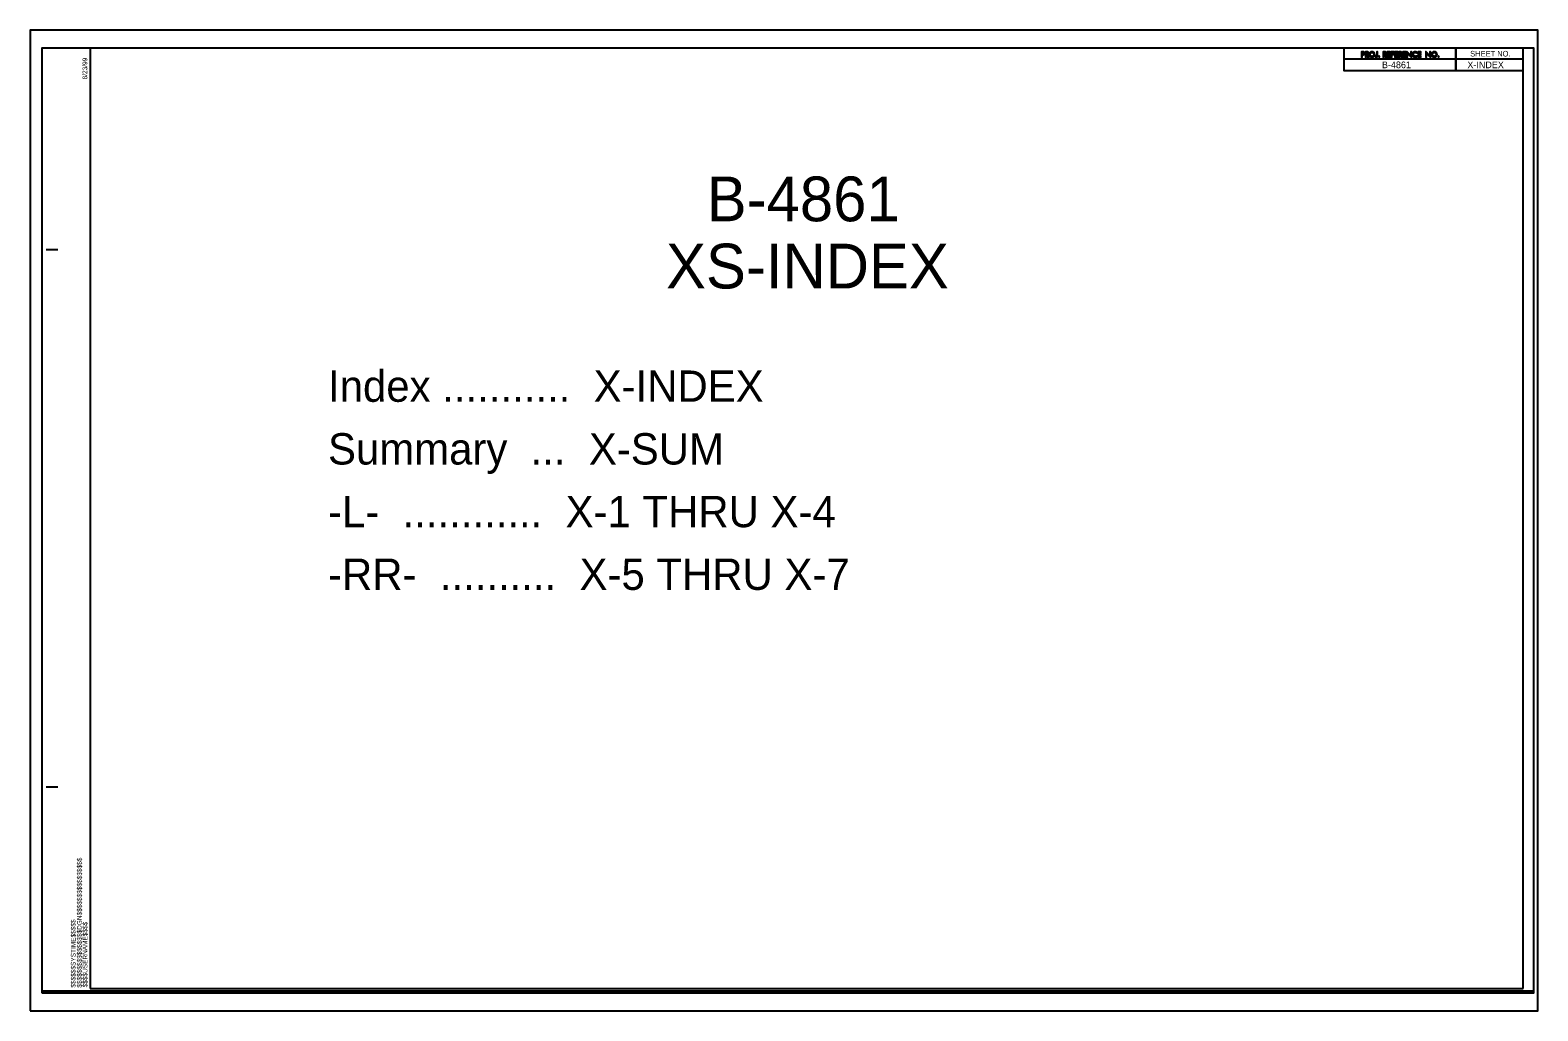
# Model space of a CAD drawing. Extents: x -13 to 323, y -5 to 214.
import ezdxf

# ---------------------------------------------------------------- set-up
doc = ezdxf.new("R2010")
doc.units = 0
for name, color, linetype in [('Old_Level_18', 7, 'Continuous'), ('Old_Level_2', 7, 'Continuous'), ('Old_Level_40', 7, 'Continuous'), ('Old_Level_41', 7, 'Continuous'), ('Old_Level_50', 7, 'Continuous'), ('Old_Level_51', 7, 'Continuous'), ('Old_Level_52', 7, 'Continuous'), ('Sheet Plot Border Inside CELL', 7, 'Continuous')]:
    doc.layers.add(name, color=color, linetype=linetype)

msp = doc.modelspace()

# ---------------------------------------------------------------- linework, layer by layer
at = {"layer": 'Old_Level_18'}
for p, q in [((320, 210), (0, 210)), ((0, 210), (0, 0)), ((320, 0), (320, 210)), ((0, 0), (0, 0)), ((0, 0), (320, 0))]:
    msp.add_line(p, q, dxfattribs=at)
at = {"layer": 'Old_Level_40'}
for p, q in [((305, 210), (305, 205)), ((305, 205), (305, 210)), ((280, 207.5), (280, 205)), ((320, 207.49), (280, 207.49)), ((280, 205), (320, 205)), ((0, 0), (0, 0)), ((0, 0), (0, 0)), ((0, 0), (0, 0)), ((0, 0), (0, 0)), ((0, 0), (0, 0))]:
    msp.add_line(p, q, dxfattribs=at)
for points in [[(320, 210), (280, 210), (280, 205), (320, 205)], [(283.9045, 208.5146), (283.9045, 207.99), (284.0817, 207.99), (284.0817, 208.5146), (284.1548, 208.5146), (284.3139, 208.5176), (284.4325, 208.5449), (284.5272, 208.6135), (284.5579, 208.6703), (284.0939, 208.6703), (284.0939, 208.6707), (284.0939, 208.676), (284.0939, 208.7017), (284.0939, 208.7165), (284.0939, 208.7604), (284.0939, 208.8377), (284.0939, 208.8438), (284.0939, 208.9199), (284.0939, 208.9589), (284.0939, 208.9733), (284.0939, 208.993), (284.0939, 208.996), (284.5628, 208.996), (284.5272, 209.062), (284.4325, 209.1301), (284.3139, 209.1574), (284.1548, 209.1604), (283.9045, 209.1604), (283.9045, 209.1574), (283.9045, 209.1301), (283.9045, 209.062), (283.9045, 208.996), (283.9045, 208.993), (283.9045, 208.9733), (283.9045, 208.9589), (283.9045, 208.9199), (283.9045, 208.8438), (283.9045, 208.8377), (283.9045, 208.7604), (283.9045, 208.7165), (283.9045, 208.7017), (283.9045, 208.676), (283.9045, 208.6707), (283.9045, 208.6703), (283.9045, 208.6135), (283.9045, 208.5449), (283.9045, 208.5176)], [(284.3605, 208.7165), (284.3492, 208.7017), (284.5747, 208.7017), (284.5829, 208.7165), (284.5899, 208.7604), (284.6026, 208.8377), (284.6014, 208.8438), (284.5891, 208.9199), (284.5829, 208.9589), (284.5751, 208.9733), (284.5749, 208.9733), (284.5643, 208.993), (284.5628, 208.996), (284.1435, 208.996), (284.2457, 208.993), (284.3283, 208.9733), (284.3431, 208.9589), (284.3836, 208.9199), (284.406, 208.8438), (284.405, 208.8377), (284.3946, 208.7604)], [(284.7757, 208.5142), (284.7757, 207.99), (284.9529, 207.99), (284.9529, 208.5142), (285.1825, 208.5142), (285.1768, 208.5218), (285.2188, 208.5294), (285.301, 208.5578), (285.3791, 208.6192), (285.3993, 208.6608), (284.9647, 208.6608), (284.9647, 208.6612), (284.9647, 208.6665), (284.9647, 208.693), (284.9647, 208.7165), (284.9647, 208.7544), (284.9647, 208.8377), (284.9647, 208.8381), (284.9647, 208.9173), (284.9647, 208.9585), (284.9647, 208.9729), (284.9647, 208.993), (284.9647, 208.9964), (285.4035, 208.9964), (285.3711, 209.0555), (285.2832, 209.1237), (285.1802, 209.1532), (285.0408, 209.1604), (284.7757, 209.1604), (284.7757, 209.1532), (284.7757, 209.1237), (284.7757, 209.0555), (284.7757, 208.9964), (284.7757, 208.993), (284.7757, 208.9729), (284.7757, 208.9585), (284.7757, 208.9173), (284.7757, 208.8381), (284.7757, 208.8377), (284.7757, 208.7544), (284.7757, 208.7165), (284.7757, 208.693), (284.7757, 208.6665), (284.7757, 208.6612), (284.7757, 208.6608), (284.7757, 208.6192), (284.7757, 208.5578), (284.7757, 208.5294), (284.7757, 208.5218)], [(284.9995, 208.9964), (285.0965, 208.993), (285.4054, 208.993), (285.4035, 208.9964)], [(285.2115, 208.7165), (285.195, 208.693), (285.4152, 208.693), (285.4268, 208.7165), (285.4321, 208.7544), (285.4438, 208.8377), (285.4436, 208.8381), (285.431, 208.9173), (285.4245, 208.9585), (285.4166, 208.9729), (285.4054, 208.993), (285.0963, 208.993), (285.1749, 208.9729), (285.1883, 208.9585), (285.2276, 208.9173), (285.2488, 208.8381), (285.2486, 208.8377), (285.2382, 208.7544)], [(286.026, 208.007), (286.2662, 207.9597), (286.5063, 208.007), (286.7016, 208.1351), (286.2658, 208.1351), (286.2436, 208.1396), (286.1018, 208.1688), (285.9639, 208.2635), (285.9147, 208.3389), (285.9145, 208.3389), (285.8703, 208.4067), (285.8385, 208.5726), (285.8385, 208.5733), (285.8703, 208.7392), (285.915, 208.8078), (285.9149, 208.8078), (285.9639, 208.8828), (286.1018, 208.9775), (286.2438, 209.007), (286.2658, 209.0116), (286.7016, 209.0116), (286.5063, 209.14), (286.0258, 209.14), (285.8306, 209.0116), (285.8238, 209.007), (285.8035, 208.9775), (285.7389, 208.8828), (285.6878, 208.8078), (285.6741, 208.7392), (285.6412, 208.5733), (285.6412, 208.5726), (285.6741, 208.4067), (285.6878, 208.3389), (285.7391, 208.2635), (285.8037, 208.1688), (285.8238, 208.1396), (285.8306, 208.1351)], [(286.266, 209.187), (286.026, 209.14), (286.5063, 209.14), (286.2662, 209.187)], [(286.2876, 209.007), (286.4298, 208.9775), (286.7287, 208.9775), (286.7086, 209.007), (286.7016, 209.0116), (286.2656, 209.0116)], [(286.2878, 208.1396), (286.2658, 208.1351), (286.7016, 208.1351), (286.7086, 208.1396), (286.7285, 208.1688), (286.7931, 208.2635), (286.8446, 208.3389), (286.858, 208.4067), (286.891, 208.5726), (286.8912, 208.5733), (286.8582, 208.7392), (286.858, 208.7392), (286.8446, 208.8078), (286.7932, 208.8828), (286.7287, 208.9775), (286.4296, 208.9775), (286.5681, 208.8828), (286.6169, 208.8078), (286.6616, 208.7392), (286.6932, 208.5733), (286.6934, 208.5726), (286.6616, 208.4067), (286.6173, 208.3389), (286.5681, 208.2635), (286.4298, 208.1688)], [(287.2506, 208.1461), (287.2173, 208.1366), (287.4927, 208.1366), (287.4965, 208.1461), (287.4983, 208.151), (287.4991, 208.1525), (287.5001, 208.1741), (287.4999, 208.1741), (287.5006, 208.1873), (287.5031, 208.2461), (287.5033, 208.2476), (287.5033, 208.3086), (287.5033, 209.1604), (287.3143, 209.1604), (287.3143, 208.3086), (287.3131, 208.2476), (287.3131, 208.2461), (287.3006, 208.1873), (287.2887, 208.1741), (287.2694, 208.1525), (287.2681, 208.151)], [(288.7417, 208.5142), (288.7417, 207.99), (288.919, 207.99), (288.919, 208.5142), (289.1485, 208.5142), (289.1428, 208.5218), (289.1849, 208.5294), (289.2671, 208.5578), (289.3451, 208.6192), (289.3654, 208.6608), (288.9307, 208.6608), (288.9307, 208.6612), (288.9307, 208.6665), (288.9307, 208.693), (288.9307, 208.7165), (288.9307, 208.7544), (288.9307, 208.8377), (288.9307, 208.8381), (288.9307, 208.9173), (288.9307, 208.9585), (288.9307, 208.9729), (288.9307, 208.993), (288.9307, 208.9964), (289.3695, 208.9964), (289.3371, 209.0555), (289.2493, 209.1237), (289.1462, 209.1532), (289.0068, 209.1604), (288.7417, 209.1604), (288.7417, 209.1532), (288.7417, 209.1237), (288.7417, 209.0555), (288.7417, 208.9964), (288.7417, 208.993), (288.7417, 208.9729), (288.7417, 208.9585), (288.7417, 208.9173), (288.7417, 208.8381), (288.7417, 208.8377), (288.7417, 208.7544), (288.7417, 208.7165), (288.7417, 208.693), (288.7417, 208.6665), (288.7417, 208.6612), (288.7417, 208.6608), (288.7417, 208.6192), (288.7417, 208.5578), (288.7417, 208.5294), (288.7417, 208.5218)], [(288.9656, 208.9964), (289.0625, 208.993), (289.3714, 208.993), (289.3695, 208.9964)], [(289.1775, 208.7165), (289.161, 208.693), (289.3813, 208.693), (289.3928, 208.7165), (289.3981, 208.7544), (289.4099, 208.8377), (289.4097, 208.8381), (289.397, 208.9173), (289.3906, 208.9585), (289.3826, 208.9729), (289.3714, 208.993), (289.0623, 208.993), (289.1409, 208.9729), (289.1544, 208.9585), (289.1936, 208.9173), (289.2148, 208.8381), (289.2146, 208.8377), (289.2042, 208.7544)], [(289.6585, 208.1605), (289.6585, 207.99), (290.3119, 207.99), (290.3119, 208.1605), (289.8479, 208.1605), (289.8479, 208.5385), (290.3119, 208.5385), (290.3119, 208.7051), (289.8479, 208.7051), (289.8479, 208.9972), (290.3119, 208.9972), (290.3119, 209.1604), (289.6585, 209.1604), (289.6585, 208.9972), (289.6585, 208.7051), (289.6585, 208.5385)], [(290.5297, 208.5404), (290.5297, 207.99), (290.7191, 207.99), (290.7191, 208.5404), (291.1831, 208.5404), (291.1831, 208.707), (290.7191, 208.707), (290.7191, 208.9972), (291.1831, 208.9972), (291.1831, 209.1604), (290.5297, 209.1604), (290.5297, 208.9972), (290.5297, 208.707)], [(291.3894, 208.1605), (291.3894, 207.99), (292.0428, 207.99), (292.0428, 208.1605), (291.5788, 208.1605), (291.5788, 208.5385), (292.0428, 208.5385), (292.0428, 208.7051), (291.5788, 208.7051), (291.5788, 208.9972), (292.0428, 208.9972), (292.0428, 209.1604), (291.3894, 209.1604), (291.3894, 208.9972), (291.3894, 208.7051), (291.3894, 208.5385)], [(292.2606, 208.5142), (292.2606, 207.99), (292.4379, 207.99), (292.4379, 208.5142), (292.6674, 208.5142), (292.6617, 208.5218), (292.7038, 208.5294), (292.786, 208.5578), (292.864, 208.6192), (292.8842, 208.6608), (292.4496, 208.6608), (292.4496, 208.6612), (292.4496, 208.6665), (292.4496, 208.693), (292.4496, 208.7165), (292.4496, 208.7544), (292.4496, 208.8377), (292.4496, 208.8381), (292.4496, 208.9173), (292.4496, 208.9585), (292.4496, 208.9729), (292.4496, 208.993), (292.4496, 208.9964), (292.8884, 208.9964), (292.856, 209.0555), (292.7682, 209.1237), (292.6651, 209.1532), (292.5257, 209.1604), (292.2606, 209.1604), (292.2606, 209.1532), (292.2606, 209.1237), (292.2606, 209.0555), (292.2606, 208.9964), (292.2606, 208.993), (292.2606, 208.9729), (292.2606, 208.9585), (292.2606, 208.9173), (292.2606, 208.8381), (292.2606, 208.8377), (292.2606, 208.7544), (292.2606, 208.7165), (292.2606, 208.693), (292.2606, 208.6665), (292.2606, 208.6612), (292.2606, 208.6608), (292.2606, 208.6192), (292.2606, 208.5578), (292.2606, 208.5294), (292.2606, 208.5218)], [(292.4844, 208.9964), (292.5814, 208.993), (292.8903, 208.993), (292.8884, 208.9964)], [(292.6964, 208.7165), (292.6799, 208.693), (292.9002, 208.693), (292.9117, 208.7165), (292.917, 208.7544), (292.9288, 208.8377), (292.9286, 208.8381), (292.9159, 208.9173), (292.9094, 208.9585), (292.9015, 208.9729), (292.8903, 208.993), (292.5812, 208.993), (292.6598, 208.9729), (292.6733, 208.9585), (292.7125, 208.9173), (292.7337, 208.8381), (292.7335, 208.8377), (292.7231, 208.7544)], [(293.1774, 208.1605), (293.1774, 207.99), (293.8308, 207.99), (293.8308, 208.1605), (293.3668, 208.1605), (293.3668, 208.5385), (293.8308, 208.5385), (293.8308, 208.7051), (293.3668, 208.7051), (293.3668, 208.9972), (293.8308, 208.9972), (293.8308, 209.1604), (293.1774, 209.1604), (293.1774, 208.9972), (293.1774, 208.7051), (293.1774, 208.5385)], [(294.0486, 208.3491), (294.0486, 207.9896), (294.2229, 207.9896), (294.2229, 208.3491), (294.2229, 208.4252), (294.2229, 208.4904), (294.2229, 208.6729), (294.2229, 208.743), (294.2229, 208.8025), (294.4672, 208.8025), (294.0486, 209.2059), (294.0486, 208.8025), (294.0486, 208.743), (294.0486, 208.6729), (294.0486, 208.4904), (294.0486, 208.4252)], [(295.0467, 207.9896), (295.0937, 207.9445), (295.0937, 207.9896), (295.0937, 208.3491), (294.9191, 208.3491), (294.8547, 208.4252), (294.791, 208.4904), (294.6015, 208.6729), (294.5287, 208.743), (294.4672, 208.8025), (294.2229, 208.8025), (294.2695, 208.743), (294.3357, 208.6729), (294.5257, 208.4904), (294.5935, 208.4252), (294.6727, 208.3491)], [(294.9191, 208.4252), (294.9191, 208.3491), (295.0937, 208.3491), (295.0937, 208.4252), (295.0937, 208.4904), (295.0937, 208.6729), (295.0937, 208.743), (295.0937, 209.1604), (294.9191, 209.1604), (294.9191, 208.743), (294.9191, 208.6729), (294.9191, 208.4904)], [(295.8128, 207.9813), (295.9367, 207.9597), (296.1147, 207.9813), (296.1668, 208.0021), (296.242, 208.032), (296.2999, 208.0684), (296.2999, 208.1328), (296.2999, 208.1351), (295.9226, 208.1351), (295.7933, 208.1597), (295.7715, 208.1639), (295.6886, 208.2173), (295.631, 208.2544), (295.58, 208.3362), (295.5378, 208.4044), (295.5094, 208.5714), (295.5094, 208.5722), (295.5401, 208.7449), (295.5819, 208.8123), (295.6211, 208.8752), (295.6295, 208.8885), (295.7101, 208.9419), (295.7715, 208.9824), (295.8234, 208.9919), (295.9355, 209.0123), (296.3084, 209.0123), (296.3084, 209.0127), (296.3113, 209.0673), (296.2317, 209.1157), (296.1562, 209.1449), (296.0984, 209.1673), (295.9117, 209.187), (295.8103, 209.1673), (295.6954, 209.1449), (295.6499, 209.1157), (295.5747, 209.0673), (295.4901, 209.0127), (295.4897, 209.0123), (295.4763, 208.9919), (295.4698, 208.9824), (295.4429, 208.9419), (295.4075, 208.8885), (295.3988, 208.8752), (295.3571, 208.8123), (295.3442, 208.7449), (295.3113, 208.5722), (295.3113, 208.5714), (295.3429, 208.4044), (295.356, 208.3362), (295.4094, 208.2544), (295.4336, 208.2173), (295.4685, 208.1639), (295.4713, 208.1597), (295.4874, 208.1351), (295.4889, 208.1328), (295.5897, 208.0684), (295.6465, 208.032), (295.6935, 208.0021)], [(296.2831, 208.8885), (296.3018, 208.8752), (296.3024, 208.8885), (296.305, 208.9419), (296.3071, 208.9824), (296.3069, 208.9824), (296.3075, 208.9919), (296.3084, 209.0123), (295.9355, 209.0123), (296.0901, 208.9919), (296.1122, 208.9824), (296.2079, 208.9419)], [(296.5372, 208.1605), (296.5372, 207.99), (297.1906, 207.99), (297.1906, 208.1605), (296.7266, 208.1605), (296.7266, 208.5385), (297.1906, 208.5385), (297.1906, 208.7051), (296.7266, 208.7051), (296.7266, 208.9972), (297.1906, 208.9972), (297.1906, 209.1604), (296.5372, 209.1604), (296.5372, 208.9972), (296.5372, 208.7051), (296.5372, 208.5385)], [(298.2794, 208.3491), (298.2794, 207.9896), (298.4537, 207.9896), (298.4537, 208.3491), (298.4537, 208.4252), (298.4537, 208.4904), (298.4537, 208.6729), (298.4537, 208.743), (298.4537, 208.8025), (298.698, 208.8025), (298.2794, 209.2059), (298.2794, 208.8025), (298.2794, 208.743), (298.2794, 208.6729), (298.2794, 208.4904), (298.2794, 208.4252)], [(299.2775, 207.9896), (299.3245, 207.9445), (299.3245, 207.9896), (299.3245, 208.3491), (299.1499, 208.3491), (299.0855, 208.4252), (299.0218, 208.4904), (298.8323, 208.6729), (298.7595, 208.743), (298.698, 208.8025), (298.4537, 208.8025), (298.5003, 208.743), (298.5665, 208.6729), (298.7565, 208.4904), (298.8243, 208.4252), (298.9035, 208.3491)], [(299.1499, 208.4252), (299.1499, 208.3491), (299.3245, 208.3491), (299.3245, 208.4252), (299.3245, 208.4904), (299.3245, 208.6729), (299.3245, 208.743), (299.3245, 209.1604), (299.1499, 209.1604), (299.1499, 208.743), (299.1499, 208.6729), (299.1499, 208.4904)], [(299.9275, 208.007), (300.1677, 207.9597), (300.4078, 208.007), (300.6031, 208.1351), (300.1673, 208.1351), (300.1451, 208.1396), (300.0033, 208.1688), (299.8654, 208.2635), (299.8161, 208.3389), (299.816, 208.3389), (299.7718, 208.4067), (299.74, 208.5726), (299.74, 208.5733), (299.7718, 208.7392), (299.8165, 208.8078), (299.8163, 208.8078), (299.8654, 208.8828), (300.0033, 208.9775), (300.1453, 209.007), (300.1673, 209.0116), (300.6031, 209.0116), (300.4078, 209.14), (299.9273, 209.14), (299.7321, 209.0116), (299.7252, 209.007), (299.705, 208.9775), (299.6404, 208.8828), (299.5893, 208.8078), (299.5756, 208.7392), (299.5427, 208.5733), (299.5427, 208.5726), (299.5756, 208.4067), (299.5893, 208.3389), (299.6406, 208.2635), (299.7052, 208.1688), (299.7252, 208.1396), (299.7321, 208.1351)], [(300.1675, 209.187), (299.9275, 209.14), (300.4078, 209.14), (300.1677, 209.187)], [(300.1891, 209.007), (300.3313, 208.9775), (300.6301, 208.9775), (300.6101, 209.007), (300.6031, 209.0116), (300.1671, 209.0116)], [(300.1892, 208.1396), (300.1673, 208.1351), (300.6031, 208.1351), (300.6101, 208.1396), (300.63, 208.1688), (300.6945, 208.2635), (300.7461, 208.3389), (300.7595, 208.4067), (300.7925, 208.5726), (300.7926, 208.5733), (300.7597, 208.7392), (300.7595, 208.7392), (300.7461, 208.8078), (300.6947, 208.8828), (300.6301, 208.9775), (300.3311, 208.9775), (300.4695, 208.8828), (300.5184, 208.8078), (300.5631, 208.7392), (300.5947, 208.5733), (300.5949, 208.5726), (300.5631, 208.4067), (300.5188, 208.3389), (300.4695, 208.2635), (300.3313, 208.1688)], [(284.2024, 208.6707), (284.1435, 208.6703), (284.5579, 208.6703), (284.5581, 208.6707)], [(284.2789, 208.676), (284.2026, 208.6707), (284.5581, 208.6707), (284.5609, 208.676)], [(284.349, 208.7017), (284.2791, 208.676), (284.5609, 208.676), (284.5747, 208.7017)], [(284.9753, 208.5142), (285.3643, 207.99), (285.5787, 207.99), (285.1825, 208.5142)], [(285.0556, 208.6612), (284.9995, 208.6608), (285.3993, 208.6608), (285.3995, 208.6612), (285.4022, 208.6665), (285.4152, 208.693), (285.1948, 208.693), (285.1283, 208.6665)], [(287.1548, 207.9669), (287.2643, 207.9597), (287.2919, 207.9669), (287.3798, 207.9896), (287.394, 208.0017), (287.4448, 208.0449), (287.4627, 208.0601), (287.4707, 208.0805), (287.4929, 208.1366), (287.2173, 208.1366), (287.1662, 208.1461), (287.1592, 208.151), (287.1569, 208.1525), (287.1264, 208.1741), (287.1135, 208.1873), (287.0995, 208.2021), (287.0847, 208.1873), (287.0715, 208.1741), (287.0499, 208.1525), (287.0484, 208.151), (287.0434, 208.1461), (287.034, 208.1366), (286.9779, 208.0805), (286.9984, 208.0601), (287.0135, 208.0449), (287.0692, 208.0017), (287.0989, 207.9896)], [(287.769, 208.0392), (287.7917, 208.0055), (287.9398, 208.0055), (287.9622, 208.0392), (287.9701, 208.079), (287.9622, 208.1192), (287.9398, 208.1529), (287.9057, 208.1752), (287.8656, 208.1832), (287.8254, 208.1752), (287.7917, 208.1529), (287.769, 208.1192), (287.761, 208.079)], [(287.8254, 207.9824), (287.8656, 207.9748), (287.9057, 207.9824), (287.9398, 208.0055), (287.7915, 208.0055)], [(288.9413, 208.5142), (289.3303, 207.99), (289.5447, 207.99), (289.1485, 208.5142)], [(289.0216, 208.6612), (288.9656, 208.6608), (289.3654, 208.6608), (289.3656, 208.6612), (289.3682, 208.6665), (289.3813, 208.693), (289.1608, 208.693), (289.0943, 208.6665)], [(292.4602, 208.5142), (292.8492, 207.99), (293.0636, 207.99), (292.6674, 208.5142)], [(292.5405, 208.6612), (292.4844, 208.6608), (292.8842, 208.6608), (292.8844, 208.6612), (292.8871, 208.6665), (292.9002, 208.693), (292.6797, 208.693), (292.6132, 208.6665)], [(296.0867, 208.1597), (295.9226, 208.1351), (296.2999, 208.1351), (296.2999, 208.1597), (296.2999, 208.1639), (296.2999, 208.2173), (296.2999, 208.2544), (296.2999, 208.2824), (296.2997, 208.2824), (296.262, 208.2544), (296.212, 208.2173), (296.0956, 208.1639)], [(301.0265, 208.0392), (301.0493, 208.0055), (301.1974, 208.0055), (301.2197, 208.0392), (301.2277, 208.079), (301.2197, 208.1192), (301.1974, 208.1529), (301.1633, 208.1752), (301.1231, 208.1832), (301.083, 208.1752), (301.0493, 208.1529), (301.0265, 208.1192), (301.0186, 208.079)], [(301.083, 207.9824), (301.1231, 207.9748), (301.1633, 207.9824), (301.1974, 208.0055), (301.0491, 208.0055)]]:
    msp.add_lwpolyline(points, close=True, dxfattribs=at)
at = {"layer": 'Old_Level_41'}
for p, q in [((-9.8, 165), (-7.3, 165)), ((-9.7, 165), (-7.2, 165)), ((-9.8, 45), (-7.3, 45)), ((-9.7, 45), (-7.2, 45))]:
    msp.add_line(p, q, dxfattribs=at)
at = {"layer": 'Old_Level_50'}
for p, q in [((323.3, 214), (323.3, 214)), ((-13.4, -5), (-13.4, -5)), ((-13.4, -5), (-13.4, -5))]:
    msp.add_line(p, q, dxfattribs=at)
msp.add_lwpolyline([(-10.8, -1), (322.4, -1), (322.4, 210), (-10.8, 210)], close=True, dxfattribs=at)
at = {"layer": 'Old_Level_51'}
msp.add_lwpolyline([(-13.4, -5), (323.3, -5), (323.3, 214), (-13.4, 214)], close=True, dxfattribs=at)
at = {"layer": 'Old_Level_52'}
for p, q in [((322.4, 210), (322.4, 210)), ((-10.8, -0.51), (-10.8, -0.51)), ((-10.8, -1), (-10.8, -1))]:
    msp.add_line(p, q, dxfattribs=at)
at = {"layer": 'Sheet Plot Border Inside CELL'}
msp.add_lwpolyline([(-10.8, -0.51), (322.4, -0.51), (322.4, 210), (-10.8, 210)], close=True, dxfattribs=at)

# ---------------------------------------------------------------- texts
at = {"layer": 'Old_Level_2'}
for s, height, p in [('B-4861', 10, (137.6812, 171.3191)), ('XS-INDEX', 10, (128.6024, 156.3191)), ('Index ...........  X-INDEX', 7, (53.1245, 131.0021)), ('Summary  ...  X-SUM', 7, (53.1245, 117.0021)), ('-L-  ............  X-1 THRU X-4', 7, (53.1245, 103.0021)), ('-RR-  ..........  X-5 THRU X-7', 7, (53.1245, 89.0021))]:
    msp.add_text(s, height=height, dxfattribs=at).set_placement(p)
at = {"layer": 'Old_Level_40'}
for s, height, p in [('SHEET NO.', 1.24998, (308.19, 208.12)), ('B-4861', 1.5, (288.4917, 205.5)), ('X-INDEX', 1.5, (307.569, 205.5))]:
    msp.add_text(s, height=height, dxfattribs=at).set_placement(p)
at = {"layer": 'Old_Level_41'}
for s, p in [('8/23/99', (-0.65, 203)), ('$$$$$$$$$$$$$$$$DGN$$$$$$$$$$$$$$$$', (-1.88, 0.18)), ('$$$$$$SYSTIME$$$$$', (-3.26, 0.18)), ('$$$$USERNAME$$$$', (-0.62, 0.23))]:
    msp.add_text(s, height=1.05, rotation=90, dxfattribs=at).set_placement(p)

doc.saveas('drawing.dxf')
